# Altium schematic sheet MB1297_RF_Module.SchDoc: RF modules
size A4; Date: Not used; ApprovedBy: Not used; CheckedBy: Not used; Author: Not used; CompanyName: STMicroelectronics; DrawnBy: Not used; Engineer: Not used; Organization: Not used; Address1: Not used; Address2: Not used; Address3: Not used; Address4: Not used; DocumentNumber: Not used; Revision: Not used; SheetNumber: 6; SheetTotal: 12
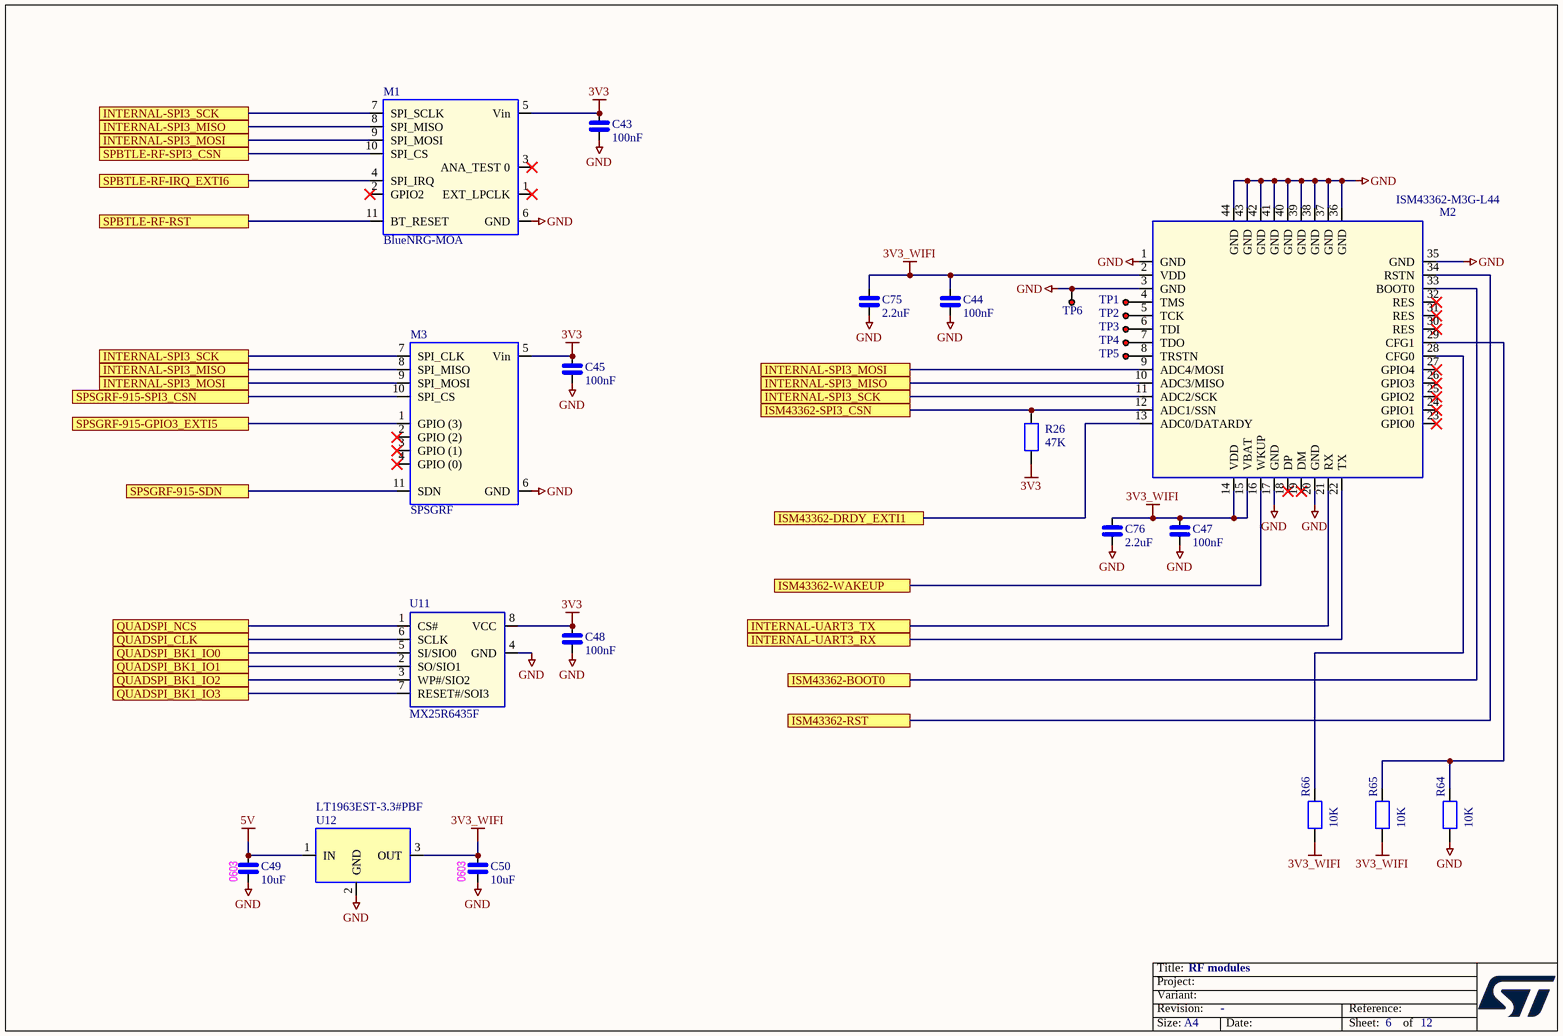
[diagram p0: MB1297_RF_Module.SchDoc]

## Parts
C43  100nF  [0402]
C44  100nF  [0402]
C45  100nF  [0402]
C47  100nF  [0402]
C48  100nF  [0402]
C49  10uF  [0603_CAP_NPOL]
C50  10uF  [0603_CAP_NPOL]
C75  2.2uF  [0603_CAP_NPOL]
C76  2.2uF  [0603_CAP_NPOL]
M1  BlueNRG-MOA  [SPBTLE-RF]
M2  ISM43362-M3G-L44  [ISM43362-M3G-L44]
M3  SPSGRF  [SPSGRF]
R26  47K  [0402]
R64  10K  [0402]
R65  10K  [0402]
R66  10K  [0402]
TP1  PT  [PTB]  (value not drawn)
TP2  PT  [PTB]  (value not drawn)
TP3  PT  [PTB]  (value not drawn)
TP4  PT  [PTB]  (value not drawn)
TP5  PT  [PTB]  (value not drawn)
TP6  PT  [PTB]  (value not drawn)
U11  MX25R6435F  [SOP8L]
U12  LT1963EST-3.3#PBF  [SOT223_SC73]

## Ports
INTERNAL-SPI3_MISO, INTERNAL-SPI3_MOSI, INTERNAL-SPI3_SCK, INTERNAL-UART3_RX, INTERNAL-UART3_TX, ISM43362-BOOT0, ISM43362-DRDY_EXTI1, ISM43362-RST, ISM43362-SPI3_CSN, ISM43362-WAKEUP, QUADSPI_BK1_IO0, QUADSPI_BK1_IO1, QUADSPI_BK1_IO2, QUADSPI_BK1_IO3, QUADSPI_CLK, QUADSPI_NCS, SPBTLE-RF-IRQ_EXTI6, SPBTLE-RF-RST, SPBTLE-RF-SPI3_CSN, SPSGRF-915-GPIO3_EXTI5, SPSGRF-915-SDN, SPSGRF-915-SPI3_CSN

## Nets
3V3: C43.1 C45.1 C48.1 M1.5(Vin) M3.5(Vin) R26.2 U11.8(VCC)
3V3_WIFI: C44.1 C47.1 C50.1 C75.1 C76.1 M2.2(VDD) M2.14(VDD) M2.15(VBAT) R65.2 R66.2 U12.3(OUT)
5V: C49.1 U12.1(IN)
GND: C43.2 C44.2 C45.2 C47.2 C48.2 C49.2 C50.2 C75.2 C76.2 M1.6(GND) M2.1(GND) M2.3(GND) M2.17(GND) M2.20(GND) M2.35(GND) M2.36(GND) M2.37(GND) M2.38(GND) M2.39(GND) M2.40(GND) M2.41(GND) M2.42(GND) M2.43(GND) M2.44(GND) M3.6(GND) R64.2 TP6.1 U11.4(GND) U12.2(GND)
INTERNAL-SPI3_MISO: M1.8(SPI_MISO) M2.10(ADC3/MISO) M3.8(SPI_MISO) ; port INTERNAL-SPI3_MISO
INTERNAL-SPI3_MOSI: M1.9(SPI_MOSI) M2.9(ADC4/MOSI) M3.9(SPI_MOSI) ; port INTERNAL-SPI3_MOSI
INTERNAL-SPI3_SCK: M1.7(SPI_SCLK) M2.11(ADC2/SCK) M3.7(SPI_CLK) ; port INTERNAL-SPI3_SCK
INTERNAL-UART3_RX: M2.22(TX) ; port INTERNAL-UART3_RX
INTERNAL-UART3_TX: M2.21(RX) ; port INTERNAL-UART3_TX
ISM43362-BOOT0: M2.33(BOOT0) ; port ISM43362-BOOT0
ISM43362-DRDY_EXTI1: M2.13(ADC0/DATARDY) ; port ISM43362-DRDY_EXTI1
ISM43362-RST: M2.34(RSTN) ; port ISM43362-RST
ISM43362-SPI3_CSN: M2.12(ADC1/SSN) R26.1 ; port ISM43362-SPI3_CSN
ISM43362-WAKEUP: M2.16(WKUP) ; port ISM43362-WAKEUP
QUADSPI_BK1_IO0: U11.5(SI/SIO0) ; port QUADSPI_BK1_IO0
QUADSPI_BK1_IO1: U11.2(SO/SIO1) ; port QUADSPI_BK1_IO1
QUADSPI_BK1_IO2: U11.3(WP#/SIO2) ; port QUADSPI_BK1_IO2
QUADSPI_BK1_IO3: U11.7(RESET#/SOI3) ; port QUADSPI_BK1_IO3
QUADSPI_CLK: U11.6(SCLK) ; port QUADSPI_CLK
QUADSPI_NCS: U11.1(CS#) ; port QUADSPI_NCS
SPBTLE-RF-IRQ_EXTI6: M1.4(SPI_IRQ) ; port SPBTLE-RF-IRQ_EXTI6
SPBTLE-RF-RST: M1.11(BT_RESET) ; port SPBTLE-RF-RST
SPBTLE-RF-SPI3_CSN: M1.10(SPI_CS) ; port SPBTLE-RF-SPI3_CSN
SPSGRF-915-GPIO3_EXTI5: M3.1(GPIO_(3)) ; port SPSGRF-915-GPIO3_EXTI5
SPSGRF-915-SDN: M3.11(SDN) ; port SPSGRF-915-SDN
SPSGRF-915-SPI3_CSN: M3.10(SPI_CS) ; port SPSGRF-915-SPI3_CSN
NetM2_4: M2.4(TMS) TP1.1
NetM2_5: M2.5(TCK) TP2.1
NetM2_6: M2.6(TDI) TP3.1
NetM2_7: M2.7(TDO) TP4.1
NetM2_8: M2.8(TRSTN) TP5.1
NetM2_28: M2.28(CFG0) R66.1
NetM2_29: M2.29(CFG1) R64.1 R65.1

Not connected (* = marked no-connect by the designer): M1 1(EXT_LPCLK)* 2(GPIO2)* 3(ANA_TEST_0)*; M2 18(DP)* 19(DM)* 23(GPIO0)* 24(GPIO1)* 25(GPIO2)* 26(GPIO3)* 27(GPIO4)* 30(RES)* 31(RES)* 32(RES)*; M3 2(GPIO_(2))* 3(GPIO_(1))* 4(GPIO_(0))*

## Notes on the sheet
- (near C49) 0603
- (near C50) 0603

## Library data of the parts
C43-C45 C47-C50 C75 C76 = CAP_NPOL: Capacitor_not polarized
M1 = SPBTLE-RF
M2 = ISM43362-M3G-L44: ISM43362-M3G-L44 Wifi Module 802.11 bgn
M3 = SPSGRF: SPSGRF-915or SPSGRF-868
R26 = RES: Resistor
R64-R66 = RES: Resistor; FITTED: NO
TP1-TP6 = PT: Point de test
U11 = MX25R6435F: MX25R6435F Serial Flash Memory 64M
U12 = LT1963EST-3.3: LT1963EST-3.3 LDO Low Noise 1.5A fast Transient Response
